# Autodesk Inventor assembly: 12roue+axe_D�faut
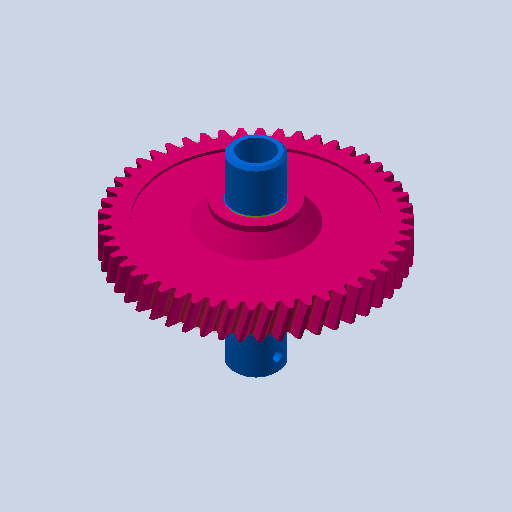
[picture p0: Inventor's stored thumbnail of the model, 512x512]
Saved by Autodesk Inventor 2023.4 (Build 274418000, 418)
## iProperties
Created: 2011-01
Part Number: 12roue+axe_D�faut
Document SubType Name: Assembly
Designer: eric
Mass: 62.4241 g
Surface Area: 248.334 cm^2
Volume: 62.4241 cm^3
Density: 1 g/cm^3
Author: eric
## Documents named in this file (3)
- C:\Users\bruno\Documents\1-Cours-2024-25\TSsI\7-Dynamique\chariot de golf\chariot_de_golf\chariot_de_golf_trolem\12roue+axe_Defaut.iam
- C:\Users\bruno\Documents\1-Cours-2024-25\TSsI\7-Dynamique\chariot de golf\chariot_de_golf\chariot_de_golf_trolem\12axe-roue-helicoidale_Defaut.ipt
- C:\Users\bruno\Documents\1-Cours-2024-25\TSsI\7-Dynamique\chariot de golf\chariot_de_golf\chariot_de_golf_trolem\12Roue helicoidale_Defaut.ipt
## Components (2 placed, 2 different names)
1. 12axe-roue-helicoidale_Defaut:1
2. 12Roue helicoidale_Defaut:1
